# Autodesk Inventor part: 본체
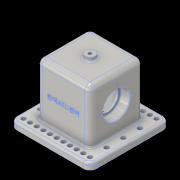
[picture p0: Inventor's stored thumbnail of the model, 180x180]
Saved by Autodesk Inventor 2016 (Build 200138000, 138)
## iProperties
Created: 2018-11
Part Number: 본체
Material: 알루미늄 6061
Document SubType Name: Modeling
Designer: PC-18
Mass: 1036.78 g
Surface Area: 772.355 cm^2
Volume: 383.993 cm^3
Density: 2.7 g/cm^3
Appearance: 알루미늄 - 평지
Author: PC-18
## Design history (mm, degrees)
sketch "스케치1"
  geometry: L1 (60, 60)-(-60, 60); L2 (-60, 60)-(-60, -60); L3 (-60, -60)-(60, -60); L4 (60, -60)-(60, 60); L5 (60, 60)-(-60, -60); L6 (-60, 60)-(60, -60); 1 further point
  constraints: 12 end point, 2 midpoint, 2 parallel, 1 horizontal, 1 perpendicular
  dimensions: "d0" = 120 distance of L3.end L2.end; "d1" = 120 distance of L2.end L1.end
extrude "돌출1" new body sketch "스케치1" distance "d2" = 10; taper "d3" = 0 deg
sketch "스케치2"
  geometry: L1 (40, 40)-(-40, 40); L2 (-40, 40)-(-40, -40); L3 (-40, -40)-(40, -40); L4 (40, -40)-(40, 40); L5 (40, 40)-(-40, -40); L6 (-40, 40)-(40, -40); 1 further point
  constraints: 12 end point, 2 midpoint, 2 parallel, 1 horizontal, 1 perpendicular
  dimensions: "d4" = 80 distance of L3.end L2.end; "d5" = 80 distance of L2.end L1.end
extrude "돌출2" join sketch "스케치2" distance "d6" = 80; taper "d7" = 0 deg
sketch "스케치3"
  geometry: L1 (-23, -30)-(23, -30); L2 (23, -30)-(23, 30); L3 (23, 30)-(-23, 30); L4 (-23, 30)-(-23, -30); L5 (-23, -30)-(23, 30); L6 (23, -30)-(-23, 30); 1 further point
  constraints: 12 end point, 2 midpoint, 2 parallel, 1 horizontal, 1 perpendicular
  dimensions: "d8" = 46 distance of L3.end L2.end; "d9" = 60 distance of L2.end L1.end
extrude "돌출3" cut sketch "스케치3" distance "d10" = 80; taper "d11" = 0 deg
sketch "스케치4"
  geometry: L1 (-10, 100)-(-10, -20) reference; C1 r 20 at (38, 40); 2 further points
  constraints: 1 centre point, 1 horizontal alignment, 1 midpoint
  dimensions: "d12" = 40 diameter of C1; "d13" = 48 distance from line of L1 C1.centre
extrude "돌출4" cut sketch "스케치4" distance "d14" = 14; taper "d15" = 0 deg
hole "구멍1" diameter "d18" = 33; stored, may be unused: countersink angle "d22" = 90 deg, drill point angle "d24" = 118 deg; dims "d16" = 10, "d17" = 10, "d19" = 6, "d20" = 33, "d21" = 2, "d23" = 8
hole "구멍2" diameter "d27" = 40; stored, may be unused: countersink angle "d31" = 90 deg, drill point angle "d33" = 0 deg; dims "d25" = 10, "d26" = 10, "d28" = 6, "d29" = 33, "d30" = 2, "d32" = 14
fillet "모깎기2" dims "d35" = 8
sketch "스케치5"
  geometry: C1 r 7.5 at (0, 0); 1 further point
  constraints: 1 centre point, 1 coincident
  dimensions: "d36" = 15 diameter of C1
extrude "돌출5" join sketch "스케치5" distance "d37" = 5; taper "d38" = 0 deg
hole "구멍3" diameter "d41" = 4.917; stored, may be unused: countersink angle "d45" = 90 deg, drill point angle "d47" = 118 deg; dims "d39" = 10, "d40" = 10, "d42" = 12, "d43" = 33, "d44" = 2, "d46" = 17.1
sketch "스케치6" dims "d48" = 52
  geometry: L1 (-10, 92)-(-10, -28) reference; 3 further points
  constraints: 1 horizontal alignment, 2 other
  dimensions: "d49" = 48 distance from line of L1 point (38, 32)
hole "구멍4" sketch "스케치6" at (64, 32) diameter "d50" = 3.242; stored, may be unused: countersink angle "d54" = 90 deg, drill point angle "d56" = 118 deg; dims "d51" = 8, "d52" = 33, "d53" = 2, "d55" = 10
chamfer "모따기1" distance "d60" = 1; stored, may be unused: second distance "d61" = 2, angle "d62" = 45 deg
fillet "모깎기3" dims "d63" = 0.6
fillet "모깎기4" dims "d64" = 10
fillet "모깎기5" dims "d65" = 3
fillet "모깎기6" dims "d66" = 8
fillet "모깎기7" dims "d67" = 3
hole "구멍5" diameter "d70" = 6.6; stored, may be unused: countersink angle "d74" = 90 deg, drill point angle "d76" = 118 deg; dims "d71" = 8, "d72" = 33, "d73" = 2, "d75" = 10, "d79" = 10, "d80" = 10
fillet "모깎기8" dims "d105" = 3
node "작업 평면1"
sketch "스케치10"
  geometry: L1 (-10.07, -30.398)-(74.07, -30.398); L2 (74.07, -30.398)-(74.07, -37.602); L3 (74.07, -37.602)-(-10.07, -37.602); L4 (-10.07, -37.602)-(-10.07, -30.398); L5 (-18, -82)-(82, -82) reference; 4 further points
  constraints: 3 midpoint, 1 vertical alignment, 2 other
  dimensions: "d107" = 48 distance from line of L5 point (-10.07, -34)
feature "엠보싱1" sketch "스케치10" dims "d0" = 120, "d1" = 120, "d8" = 46, "d9" = 60, "d108" = 0.5, "d109" = 0
fillet "모깎기9" dims "d110" = 3
node "솔리드1"
pattern_circular "원형 패턴1" dims angle "d58" = 360 deg
mirror "대칭1"
pattern_linear "직사각형 패턴2" dims "d113" = 10
mirror "대칭4"
pattern_linear "직사각형 패턴3" dims "d116" = 25
mirror "대칭5"
other parameters: "d106" = 12
